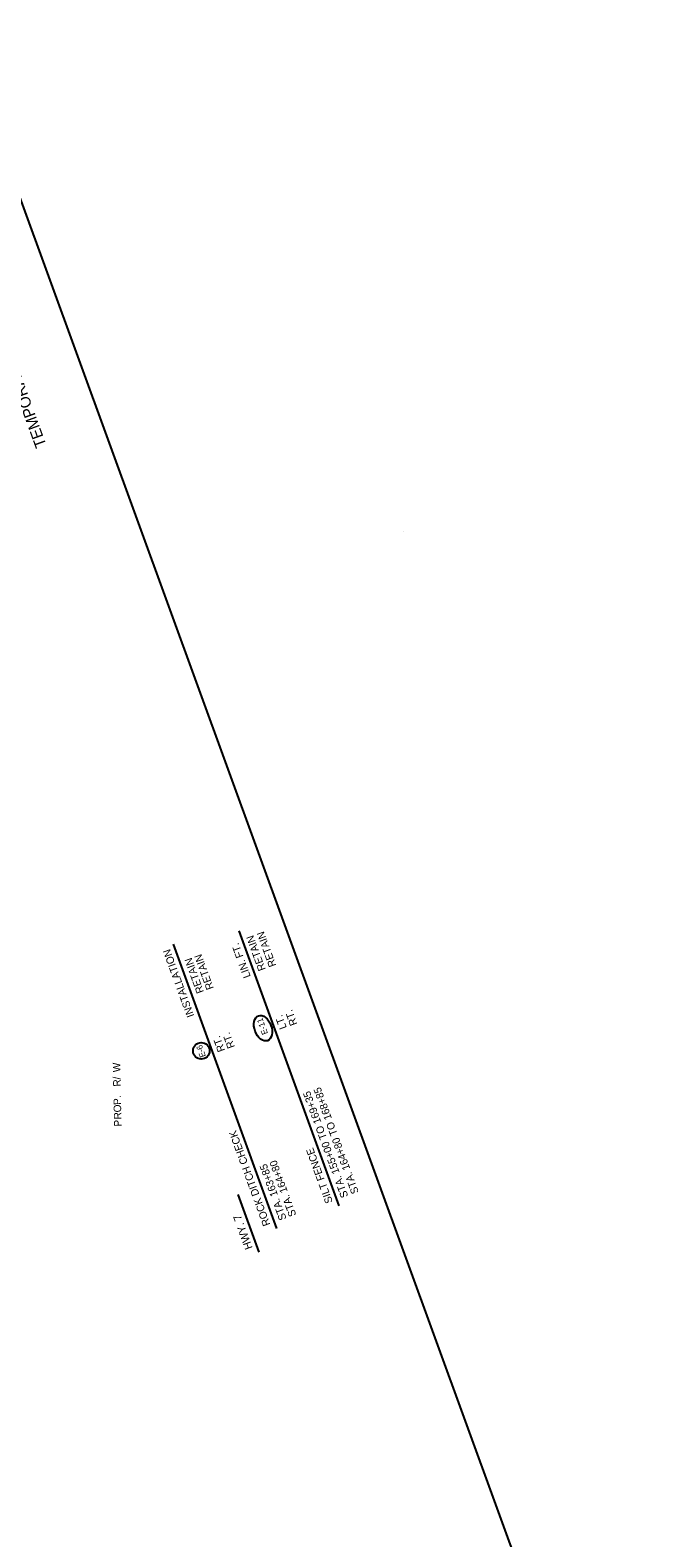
# Model space of a CAD drawing. Extents: x 986289 to 987754, y 1870781 to 1872971.
# Drawn here: x 987265 to 987754, y 1871771 to 1872971 of the extents above; entities that cross this region are included whole.
import ezdxf

# ---------------------------------------------------------------- set-up
doc = ezdxf.new("R2010")
doc.units = 0
for name, color, linetype in [('1', 7, 'Continuous'), ('44', 7, 'Continuous'), ('60', 7, 'Continuous'), ('NO PLOT', 7, 'Continuous'), ('R_Draft', 7, 'Continuous')]:
    doc.layers.add(name, color=color, linetype=linetype)

msp = doc.modelspace()

# ---------------------------------------------------------------- linework, layer by layer
at = {"layer": '1'}
msp.add_line((987561.3, 1872572.4), (987561.3, 1872572.4), dxfattribs=at)
msp.add_line((987561.3, 1872572.4), (987561.3, 1872572.4), dxfattribs=at)
msp.add_circle((987400.8, 1872158.9), 6.61, dxfattribs=at)
msp.add_ellipse((987449.9, 1872176.9), major_axis=(-3.6, 9.89), ratio=0.638788, dxfattribs=at)
at = {"layer": '44'}
for p, q in [((987510.6, 1872035.5), (987431, 1872254.3)), ((987461, 1872017.4), (987378.6, 1872243.9)), ((987446.9, 1871998.8), (987430.2, 1872044.7))]:
    msp.add_line(p, q, dxfattribs=at)
at = {"layer": 'NO PLOT'}
msp.add_lwpolyline([(987753.7, 1871472.1), (987208, 1872971.2), (986718.3, 1872793), (986821.2, 1872510.2), (986884.7, 1872533.2), (987030, 1872133.9), (986966.6, 1872110.8), (987064.5, 1871841.9), (987122.5, 1871863), (987239.7, 1871541), (987181.7, 1871519.9), (987263.9, 1871293.8)], close=True, dxfattribs=at)
msp.add_lwpolyline([(987753.7, 1871472.1), (987208, 1872971.2), (986718.3, 1872793), (986821.2, 1872510.2), (986884.7, 1872533.2), (987030, 1872133.9), (986966.6, 1872110.8), (987064.5, 1871841.9), (987122.5, 1871863), (987239.7, 1871541), (987181.7, 1871519.9), (987263.9, 1871293.8)], close=True, dxfattribs=at)
msp.add_lwpolyline([(987753.7, 1871472.1), (987208, 1872971.2), (986718.3, 1872793), (986821.2, 1872510.2), (986884.7, 1872533.2), (987030, 1872133.9), (986966.6, 1872110.8), (987064.5, 1871841.9), (987122.5, 1871863), (987239.7, 1871541), (987181.7, 1871519.9), (987263.9, 1871293.8)], close=True, dxfattribs=at)
msp.add_lwpolyline([(987753.7, 1871472.1), (987208, 1872971.2), (986718.3, 1872793), (986821.2, 1872510.2), (986884.7, 1872533.2), (987030, 1872133.9), (986966.6, 1872110.8), (987064.5, 1871841.9), (987122.5, 1871863), (987239.7, 1871541), (987181.7, 1871519.9), (987263.9, 1871293.8)], close=True, dxfattribs=at)
msp.add_lwpolyline([(987753.7, 1871472.1), (987208, 1872971.2), (986718.3, 1872793), (986821.2, 1872510.2), (986884.7, 1872533.2), (987030, 1872133.9), (986966.6, 1872110.8), (987064.5, 1871841.9), (987122.5, 1871863), (987239.7, 1871541), (987181.7, 1871519.9), (987263.9, 1871293.8)], close=True, dxfattribs=at)

# ---------------------------------------------------------------- texts
at = {"layer": '1'}
for s, p in [('E-11', (987453.9, 1872172.8)), ('E-6 ', (987404.5, 1872154.7))]:
    msp.add_text(s, height=4.8, rotation=110, dxfattribs=at).set_placement(p)
at = {"layer": '44'}
for s, height, p in [('LIN. FT.', 6, (987440.2, 1872218.1)), ('RETAIN', 6, (987452.1, 1872223.8)), ('RETAIN', 6, (987460.5, 1872226.9)), ('INSTALLATION', 6, (987395.3, 1872186.8)), ('RETAIN', 6, (987403, 1872205.9)), ('RETAIN', 6, (987410.8, 1872208.8)), ('LT.', 6, (987468.9, 1872177.3)), ('RT.', 6, (987477.3, 1872180.2)), ('RT.', 6, (987427.6, 1872162.1)), ('RT.', 6, (987419.8, 1872159.3)), ('STA. 155+00 TO 169+35', 6, (987517.8, 1872043.2)), ('STA. 164+80 TO 168+85', 6, (987526.2, 1872046.3)), ('ROCK DITCH CHECK', 6, (987455.8, 1872020.7)), ('SILT FENCE      ', 6, (987505.5, 1872038.7)), ('STA. 163+85', 6, (987468.7, 1872025.3)), ('STA. 164+80', 6, (987476.5, 1872028.2)), ('HWY. 7', 6.25, (987441.7, 1872002.1))]:
    msp.add_text(s, height=height, rotation=110, dxfattribs=at).set_placement(p)
at = {"layer": '60'}
msp.add_text('TEMPORARY EROSION CONTROL DETAILS', height=9, rotation=110, dxfattribs=at).set_placement((987277.8, 1872640.8))
at = {"layer": 'R_Draft'}
for s, p in [('W', (987336.5, 1872142)), ('/', (987336.6, 1872136.2)), ('R', (987336.7, 1872130.5)), ('P', (987337, 1872115.9)), ('O', (987337.1, 1872110)), ('.', (987336.9, 1872121.6)), ('R', (987337.3, 1872104.4)), ('P', (987337.4, 1872098.7))]:
    msp.add_text(s, height=6, rotation=91.2073, dxfattribs=at).set_placement(p)

doc.saveas('drawing.dxf')
